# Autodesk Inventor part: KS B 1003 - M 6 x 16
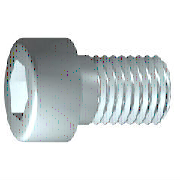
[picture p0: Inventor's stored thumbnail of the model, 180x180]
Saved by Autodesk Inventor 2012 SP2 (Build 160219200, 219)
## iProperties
Created: 2009-02
Part Number: KS B 1003 - M 6 x 16
Material: Steel, Mild
Description: 6각머리 태핑 나사
Document SubType Name: Modeling
Standard: KS B 1003
Designer: KYOUNG IL JANG
Standards Organization: KS
Language: ko-KR
Size Designation: M 6 x 16
Categories: <MemberInstance><Categories><Category DisplayName="조임쇠" InternalName="e4da775c-781d-43d5-af7c-5136215cf5a6" Mnemonic="FSTN"><Category DisplayName="볼트" InternalN
Density: 1 g/cm^3
Company: 한국ATC센터
IsCustomPart: 0
Author: KYOUNG IL JANG
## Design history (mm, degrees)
body "Solid1"
workplane "Work Plane1"
fillet "Fillet2" dims "d30" = 0.1 (= R)
revolve "본체" stored, may be unused: angle "d10" = 90 deg
sketch "스케치2"
  geometry: L1 (0, -7)-(0, 7) reference; L2 (-7, 0)-(7, 0) reference; L3 (2.887, 0)-(1.443, -2.5); L4 (1.443, -2.5)-(-1.443, -2.5); L5 (-1.443, -2.5)-(-2.887, 0); L6 (-2.887, 0)-(-1.443, 2.5); L7 (-1.443, 2.5)-(1.443, 2.5); L8 (1.443, 2.5)-(2.887, 0); 2 further points
  constraints: 12 end point, 1 coincident, 1 horizontal alignment, 1 point on line, 12 other
extrude "슬롯" join sketch "스케치2" stored distance "d11" = 10; taper "d12" = 0 deg
fillet "모깎기1" dims "d17" = 0.6 (= RR)
feature "스레드" dims "d13" = 13.5 (= GEL), "d14" = 0
chamfer "모따기1" distance "d15" = 0.61345 (= -0.5 x SPD + 0.5 x GD); stored, may be unused: second distance "d16" = 0.61345 (= GUL), angle "d27" = 45 deg
sketch "스케치1"
  geometry: L1 (-1.333, 0)-(16, 0); L2 (16, 0)-(16, 3); L3 (16, 3)-(2.5, 3); L4 (2.5, 3)-(1.886, 3); L5 (1.886, 3)-(0, 3); L6 (0, 3)-(0, 5); L7 (0, 5)-(-6, 5); L8 (-6, 5)-(-6, 2.887); L9 (-6, 2.887)-(-3, 2.887); L10 (-3, 2.887)-(-1.333, 0); L11 (-10.4, 0)-(20.4, 0) reference; L12 (0, -1)-(0, 6) reference; L13 (2.5, 3)-(0, 3)
  constraints: 22 end point, 6 parallel, 2 collinear, 2 perpendicular, 1 horizontal, 1 point on line
  dimensions: "d1" = 13.5 distance from line of L3.end L2 (= GEL); "d2" = 0.61355 distance of L4.end L3.end (computed from GAL); "d3" = 6 distance between parallel lines of L8 L6 (= KOH); "d4" = 3 distance of L8.end L9.end (= INTI); "d5" = 60 deg angle of L10 L1; "d6" = 6 diameter of L3 L1 (= GD); "d7" = 6 diameter of L5 L1 (= BDM); "d8" = 5.7735 diameter of L9 L1 (= 1.1547 x SW); "d9" = 10 diameter of L7 L1 (= KOD); "d26" = 16 distance between parallel lines of L12 L2 (= NLG)
other parameters: "GD" = 6 (= NND) [user parameter; used in 2 equation terms], "NLG" = 16 [user parameter; used in 1 equation term], "GEL" = 13.5 [user parameter; used in 2 equation terms], "KOD" = 10 [user parameter; used in 1 equation term], "KOH" = 6 [user parameter; used in 1 equation term], "INTI" = 3 [user parameter; used in 1 equation term], "GAL" = 0.61345 (= 0.61345 x PTC) [user parameter; used in 1 equation term], "GUL" = 0.61345 (= 0.61345 x PTC) [user parameter; used in 1 equation term], "BDM" = 6 (= NND) [user parameter; used in 1 equation term], "SW" = 5 [user parameter; used in 2 equation terms], "RR" = 0.6 [user parameter; used in 1 equation term], "SPD" = 4.7731 (= NND - 1.2269 x PTC) [user parameter; used in 1 equation term], "d19" = 0, "d28" = 0, "d29" = 0, "R" = 0.1 [user parameter; used in 1 equation term], "PHH" = 0.25 [user parameter], "GD1" = 4.7731 (= THREADDIA - 1.2269 x PTC) [user parameter], "THREADDIA" = 6 [user parameter; used in 1 equation term], "FAWI" = 45 deg [user parameter], "PTC" = 1 [user parameter; used in 5 equation terms], "NND" = 6 [user parameter; used in 3 equation terms], "TOA" = 30 deg [user parameter], "E0" = 5.775 (= 1.155 x SW) [user parameter]
